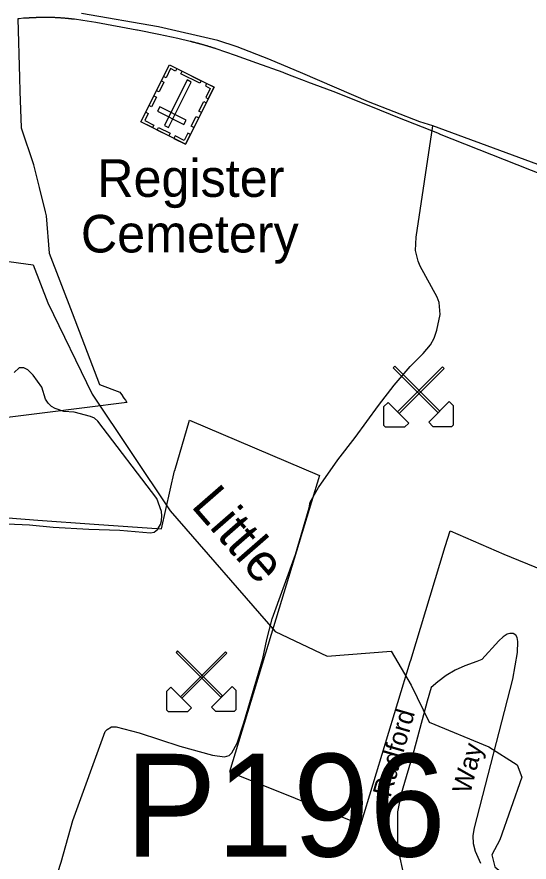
# Model space of a CAD drawing. Extents: x 2104537 to 2336408, y 34176 to 229611.
# Drawn here: x 2180556 to 2182600, y 64904 to 68278 of the extents above; entities that cross this region are included whole.
import ezdxf

# ---------------------------------------------------------------- set-up
doc = ezdxf.new("R2010")
doc.units = 0
for name, color, linetype in [('Exist Boundary Political City Limit New', 7, 'Continuous'), ('Exist Cultural Cemetery CELL', 7, 'Continuous'), ('Exist Cultural Cemetery Label', 7, 'Continuous'), ('Exist Geographical Pit Clay CELL', 7, 'Continuous'), ('Exist Hydrographic Creek Single Shore', 7, 'Continuous'), ('Exist Road Non-System Type 51', 7, 'Continuous'), ('Exist Road Non-System Type 51 Label', 7, 'Continuous'), ('Exist Road Secondary Structure Pipe Number Label', 7, 'Continuous'), ('Exist Road Secondary Type 51 Attributed', 7, 'Continuous'), ('Map Preparation Boundary City Limit Buffer Line', 7, 'Continuous'), ('Old_Level_32', 7, 'Continuous')]:
    doc.layers.add(name, color=color, linetype=linetype)

msp = doc.modelspace()

# ---------------------------------------------------------------- linework, layer by layer
at = {"layer": 'Exist Boundary Political City Limit New'}
for points in [[(2180745.8, 68272.1), (2180744, 68272.3), (2180741.8, 68272.5), (2180740, 68272.6), (2180738, 68272.8), (2180736, 68272.9), (2180734, 68273.1), (2180732, 68273.2), (2180730, 68273.4), (2180728, 68273.5), (2180726, 68273.6), (2180724, 68273.7), (2180722, 68273.9), (2180720, 68274), (2180718, 68274.1), (2180716, 68274.2), (2180714, 68274.3), (2180712, 68274.4), (2180710, 68274.5), (2180708, 68274.6), (2180706, 68274.7), (2180704, 68274.7), (2180702, 68274.8), (2180700, 68274.9), (2180698, 68275), (2180696, 68275), (2180694, 68275.1), (2180692, 68275.1), (2180690, 68275.2), (2180688, 68275.2), (2180686, 68275.2), (2180684, 68275.3), (2180682, 68275.3), (2180680, 68275.3), (2180678, 68275.4), (2180676, 68275.4), (2180673, 68275.4), (2180671, 68275.4), (2180669, 68275.4), (2180667, 68275.3), (2180665, 68275.3), (2180663, 68275.3), (2180661, 68275.3), (2180659, 68275.2), (2180657, 68275.2), (2180655, 68275.2), (2180653, 68275.1), (2180651, 68275.1), (2180649, 68275), (2180647, 68275), (2180645, 68275), (2180643, 68274.9), (2180641, 68274.8), (2180639, 68274.8), (2180637, 68274.7), (2180635, 68274.6), (2180633, 68274.6), (2180631, 68274.5), (2180629, 68274.4), (2180627, 68274.4), (2180625, 68274.3), (2180623, 68274.2), (2180621, 68274.1), (2180619, 68274), (2180617, 68273.9), (2180615, 68273.8), (2180613, 68273.7), (2180611, 68273.6), (2180609, 68273.5), (2180607, 68273.4), (2180606.2, 68273.4), (2180605, 68273.3), (2180603, 68273.2), (2180601.2, 68273.1), (2180599, 68273), (2180597, 68272.8), (2180595.2, 68272.7), (2180593.2, 68272.6), (2180591.2, 68272.5), (2180589.2, 68272.3), (2180587.2, 68272.2), (2180585.2, 68272.1), (2180582.2, 68271.9), (2180564.5, 68270.3), (2180559.2, 68269.8), (2180566.5, 68036), (2180568.2, 67979.9), (2180572.8, 67836.2), (2180573.2, 67835.2), (2180622.2, 67688.4), (2180622.5, 67687.7), (2180644.5, 67596.3), (2180668.5, 67500), (2180672.5, 67483.5), (2180672.5, 67482.9), (2180684.8, 67334.2), (2180776, 67096), (2180885.2, 66810.6), (2180966.8, 66779.9), (2180977.2, 66764.8)], [(2182711.5, 67624.2), (2182243, 67810), (2182242.2, 67810.3), (2182076.5, 67876), (2182047.8, 67887.6), (2182004.5, 67905), (2181922.5, 67938), (2181818, 67979.4), (2181717.8, 68017.1), (2181703.5, 68022.6), (2181654.8, 68041.6), (2181623.8, 68053.4), (2181619.2, 68055.1), (2181514, 68093.2), (2181428.8, 68123.9), (2181351, 68150.4), (2181349.2, 68151), (2181347.2, 68151.6), (2181345.2, 68152.2), (2181343.5, 68152.9), (2181341.5, 68153.4), (2181339.8, 68154), (2181337.8, 68154.6), (2181335.8, 68155.2), (2181334, 68155.8), (2181332, 68156.4), (2181330, 68157), (2181328.2, 68157.6), (2181326.2, 68158.2), (2181324.2, 68158.7), (2181322.5, 68159.3), (2181320.5, 68159.9), (2181318.5, 68160.5), (2181316.8, 68161), (2181314.8, 68161.6), (2181312.8, 68162.2), (2181311, 68162.7), (2181309, 68163.3), (2181307, 68163.8), (2181305.2, 68164.4), (2181303.2, 68164.9), (2181301.2, 68165.5), (2181299.5, 68166), (2181297.5, 68166.6), (2181295.5, 68167.1), (2181293.5, 68167.7), (2181291.8, 68168.2), (2181289.8, 68168.7), (2181287.8, 68169.2), (2181286, 68169.8), (2181284, 68170.3), (2181282, 68170.8), (2181280, 68171.4), (2181278.2, 68171.9), (2181276.2, 68172.4), (2181274.2, 68172.9), (2181272.5, 68173.4), (2181270.5, 68173.9), (2181268.5, 68174.4), (2181266.5, 68174.9), (2181264.8, 68175.4), (2181262.8, 68175.9), (2181260.8, 68176.4), (2181258.8, 68176.9), (2181257, 68177.4), (2181255, 68177.9), (2181253, 68178.4), (2181251, 68178.9), (2181247.2, 68179.8), (2181198.5, 68191.1), (2181122, 68207.9), (2181037.2, 68224), (2181034, 68224.6), (2180870.5, 68255.8), (2180819.5, 68263.4), (2180785.8, 68267.9), (2180783.8, 68268.1), (2180781.8, 68268.4), (2180779.8, 68268.6), (2180777.8, 68268.9), (2180775.8, 68269.1), (2180773.8, 68269.3), (2180771.8, 68269.5), (2180769.8, 68269.8), (2180767.8, 68270), (2180765.8, 68270.2), (2180763.8, 68270.4), (2180761.8, 68270.6), (2180759.8, 68270.8), (2180757.8, 68271), (2180755.8, 68271.2), (2180753.8, 68271.4), (2180751.8, 68271.6), (2180749.8, 68271.8), (2180747.8, 68272), (2180745.8, 68272.1)], [(2180977.2, 66764.8), (2180978, 66763.6), (2180983, 66756.2), (2180989, 66747.6), (2180995, 66738.8), (2180656.2, 66696.1), (2180281.5, 66648.9)], [(2180215.2, 66301.5), (2180639, 66269.3), (2180865, 66253.2), (2181133.5, 66234.1), (2181185.2, 66465.3), (2181185.8, 66467.5), (2181245.2, 66667.8), (2181763.8, 66447.4), (2181571, 65812), (2181404.8, 65263.7), (2181929.2, 65054), (2182126, 65702.8), (2182128, 65709.4), (2182265.8, 66163.1), (2182284.8, 66226.2), (2182500, 66133.2), (2182652.5, 66070.6)]]:
    msp.add_lwpolyline(points, dxfattribs=at)
at = {"layer": 'Exist Cultural Cemetery CELL'}
for points in [[(2181229, 67769.6), (2181050.9, 67858.7), (2181164.9, 68086.4), (2181342.9, 67997.3)], [(2181194.5, 68071.6), (2181189.4, 68061.3), (2181169.7, 68071.2), (2181151.6, 68035), (2181141.7, 68040), (2181164.9, 68086.4)], [(2181286.4, 68012.8), (2181210.5, 68050.7), (2181215.6, 68060.9), (2181291.5, 68023)], [(2181142.7, 68016.7), (2181123.3, 67978), (2181113.1, 67983.1), (2181132.5, 68021.8)], [(2181144.6, 67844.6), (2181161.3, 67836.2), (2181252, 68017.6), (2181235.3, 68025.9)], [(2181313.3, 68012.1), (2181308.2, 68001.8), (2181327.9, 67992), (2181309.8, 67955.8), (2181319.7, 67950.8), (2181342.9, 67997.2)], [(2181113.2, 67957.8), (2181093.8, 67919), (2181083.6, 67924.1), (2181103, 67962.9)], [(2181222.9, 67848.7), (2181231.3, 67865.4), (2181126, 67918.1), (2181117.6, 67901.4)], [(2181311.7, 67934.8), (2181292.3, 67896), (2181282.1, 67901.1), (2181301.5, 67939.8)], [(2181070.3, 67897.5), (2181080.4, 67892.4), (2181066, 67863.7), (2181102.3, 67845.5), (2181097.3, 67835.6), (2181050.9, 67858.8)], [(2181281.6, 67874.6), (2181262.2, 67835.9), (2181252, 67841), (2181271.4, 67879.7)], [(2181162.7, 67802.8), (2181116.4, 67826), (2181121.5, 67836.2), (2181167.8, 67813)], [(2181248.4, 67808.3), (2181238.2, 67813.4), (2181223.8, 67784.6), (2181187.5, 67802.8), (2181182.5, 67792.8), (2181229, 67769.6)]]:
    msp.add_lwpolyline(points, close=True, dxfattribs=at)
at = {"layer": 'Exist Geographical Pit Clay CELL'}
for points in [[(2182237.8, 66697.7), (2182243.6, 66703.5), (2182064, 66883.1), (2182058.2, 66877.3)], [(2182081.5, 66694.7), (2182075.7, 66700.5), (2182255.3, 66880.1), (2182261.1, 66874.3)], [(2182021, 66646.6), (2182021, 66722.3), (2182037.5, 66738.8), (2182119.8, 66656.5), (2182103.3, 66640), (2182027.6, 66640)], [(2182298.3, 66649.6), (2182298.3, 66725.3), (2182281.9, 66741.8), (2182199.6, 66659.5), (2182216, 66643), (2182291.7, 66643)], [(2181370.7, 65561.1), (2181376.6, 65566.9), (2181197, 65746.5), (2181191.2, 65740.7)], [(2181214.5, 65558.1), (2181208.7, 65563.9), (2181388.2, 65743.5), (2181394.1, 65737.7)], [(2181154, 65510), (2181154, 65585.7), (2181170.4, 65602.2), (2181252.7, 65519.9), (2181236.3, 65503.4), (2181160.5, 65503.4)], [(2181431.3, 65513), (2181431.3, 65588.7), (2181414.8, 65605.1), (2181332.5, 65522.8), (2181349, 65506.4), (2181424.7, 65506.4)]]:
    msp.add_lwpolyline(points, close=True, dxfattribs=at)
at = {"layer": 'Exist Hydrographic Creek Single Shore'}
msp.add_lwpolyline([(2179224.4, 66596.1), (2179424.4, 66713.7), (2179730.5, 67108), (2179879.4, 67200.3), (2180062.5, 67275.5), (2180395.5, 67318.3), (2180620.4, 67287.7), (2180679.5, 67135.6), (2180856.4, 66771.3), (2181167.5, 66306), (2181586.4, 65824.7), (2181795, 65725.9), (2182050.3, 65745.1), (2182129.8, 65610.5), (2182201.2, 65462.2), (2182440, 65363.4), (2182552.5, 65292), (2182571.7, 65242.5), (2182483.9, 64992.6), (2182451, 64932.2), (2182463.2, 64885.4), (2182494.9, 64858.1), (2182505.9, 64794.9), (2182559.6, 64740.4)], dxfattribs=at)
at = {"layer": 'Exist Road Non-System Type 51'}
for points in [[(2180690, 64771.2), (2180732.9, 64903.9), (2180779.4, 65070), (2180908.3, 65425.4), (2180916.4, 65433.5), (2180933.3, 65443.3), (2180952, 65443.9), (2181044.1, 65420.2), (2181206.7, 65365.9), (2181336.6, 65330.9), (2181385.1, 65324.4), (2181403.2, 65329.6), (2181413.3, 65339.6), (2181435, 65377.9), (2181462.2, 65460), (2181537.7, 65716.8), (2181553.2, 65792.9), (2181574.5, 65875.2), (2181668.4, 66131.9), (2181722.5, 66318.5), (2181726.2, 66340.8), (2181759.8, 66398.9), (2181836.8, 66509.6), (2181906.1, 66598.1), (2181998.8, 66726.9), (2182062.3, 66807.7), (2182125.5, 66882.3), (2182177, 66934.5), (2182206.8, 66969), (2182221.5, 66995.3), (2182232.3, 67027.2), (2182245.3, 67089.6), (2182241.3, 67137.3), (2182233.5, 67159.4), (2182166, 67282.8), (2182157.8, 67302.6), (2182147.5, 67344.5), (2182149.8, 67398.3), (2182216.5, 67842.2)], [(2180517.5, 66253.5), (2180605.7, 66249.9), (2180700.3, 66241.1), (2180843.2, 66232.8), (2180967.1, 66228.1), (2181089.6, 66217.9), (2181103.5, 66221.2), (2181116.5, 66231.8), (2181129, 66251.6), (2181132.9, 66265.6), (2181134.9, 66285.6), (2181132.6, 66303.7), (2181114.3, 66355.2), (2180879.4, 66663.6), (2180865.2, 66675.3), (2180849.6, 66682.5), (2180784.3, 66699.2), (2180743, 66702.3), (2180708.8, 66714.1), (2180694.2, 66721.9), (2180680.7, 66735.6), (2180670.5, 66751.6), (2180655, 66799.8), (2180621.5, 66847.3), (2180599.9, 66868.1), (2180583.6, 66877.3), (2180565.3, 66876.6), (2180545.6, 66858.7)], [(2182407.4, 64898.5), (2182386.7, 64946.1), (2182378.1, 64976.8), (2182376.7, 65009.9), (2182381.9, 65040), (2182534.8, 65633.6), (2182553.5, 65739.8), (2182555.4, 65783.8), (2182553.4, 65799.9), (2182547, 65809.5), (2182537.3, 65816.3), (2182522.9, 65816.5), (2182513, 65813.4), (2182497, 65803.3), (2182479.3, 65786.9), (2182411.9, 65712.4), (2182391.2, 65703.9), (2182343.5, 65687.2), (2182305.3, 65670.5), (2182269.5, 65649), (2182236.1, 65622.7), (2182209.9, 65601.3), (2182193.2, 65546.3), (2182140.7, 65348.2), (2182089.4, 65176.3), (2182075.1, 65104.7), (2182075.1, 64963.9), (2182112.5, 64793.3)]]:
    msp.add_lwpolyline(points, dxfattribs=at)
at = {"layer": 'Exist Road Secondary Type 51 Attributed'}
msp.add_lwpolyline([(2185228.9, 67698.8), (2184857.8, 67518.4), (2184683.7, 67443.7), (2184607, 67414.7), (2184546.9, 67402.2), (2184466.1, 67391.9), (2184304.4, 67381.5), (2183989.9, 67371.1), (2183730.8, 67364.9), (2183627.2, 67362.8), (2183554.6, 67364.9), (2183475.8, 67379.4), (2183388.8, 67398.1), (2183287.2, 67435.4), (2182928.6, 67580.6), (2182216.5, 67842.2), (2182164.3, 67859.3), (2181959.8, 67938.3), (2181697.2, 68051.6), (2181562.1, 68108.7), (2181434.6, 68158.2), (2181358.5, 68183), (2181120.6, 68238.2), (2180814.2, 68291.5)], dxfattribs=at)
at = {"layer": 'Map Preparation Boundary City Limit Buffer Line'}
for points in [[(2180745.8, 68272.1), (2180744, 68272.3), (2180741.8, 68272.5), (2180740, 68272.6), (2180738, 68272.8), (2180736, 68272.9), (2180734, 68273.1), (2180732, 68273.2), (2180730, 68273.4), (2180728, 68273.5), (2180726, 68273.6), (2180724, 68273.7), (2180722, 68273.9), (2180720, 68274), (2180718, 68274.1), (2180716, 68274.2), (2180714, 68274.3), (2180712, 68274.4), (2180710, 68274.5), (2180708, 68274.6), (2180706, 68274.7), (2180704, 68274.7), (2180702, 68274.8), (2180700, 68274.9), (2180698, 68275), (2180696, 68275), (2180694, 68275.1), (2180692, 68275.1), (2180690, 68275.2), (2180688, 68275.2), (2180686, 68275.2), (2180684, 68275.3), (2180682, 68275.3), (2180680, 68275.3), (2180678, 68275.4), (2180676, 68275.4), (2180673, 68275.4), (2180671, 68275.4), (2180669, 68275.4), (2180667, 68275.3), (2180665, 68275.3), (2180663, 68275.3), (2180661, 68275.3), (2180659, 68275.2), (2180657, 68275.2), (2180655, 68275.2), (2180653, 68275.1), (2180651, 68275.1), (2180649, 68275), (2180647, 68275), (2180645, 68275), (2180643, 68274.9), (2180641, 68274.8), (2180639, 68274.8), (2180637, 68274.7), (2180635, 68274.6), (2180633, 68274.6), (2180631, 68274.5), (2180629, 68274.4), (2180627, 68274.4), (2180625, 68274.3), (2180623, 68274.2), (2180621, 68274.1), (2180619, 68274), (2180617, 68273.9), (2180615, 68273.8), (2180613, 68273.7), (2180611, 68273.6), (2180609, 68273.5), (2180607, 68273.4), (2180606.2, 68273.4), (2180605, 68273.3), (2180603, 68273.2), (2180601.2, 68273.1), (2180599, 68273), (2180597, 68272.8), (2180595.2, 68272.7), (2180593.2, 68272.6), (2180591.2, 68272.5), (2180589.2, 68272.3), (2180587.2, 68272.2), (2180585.2, 68272.1), (2180582.2, 68271.9), (2180564.5, 68270.3), (2180559.2, 68269.8), (2180566.5, 68036), (2180568.2, 67979.9), (2180572.8, 67836.2), (2180573.2, 67835.2), (2180622.2, 67688.4), (2180622.5, 67687.7), (2180644.5, 67596.3), (2180668.5, 67500), (2180672.5, 67483.5), (2180672.5, 67482.9), (2180684.8, 67334.2), (2180776, 67096), (2180885.2, 66810.6), (2180966.8, 66779.9), (2180977.2, 66764.8)], [(2182711.5, 67624.2), (2182243, 67810), (2182242.2, 67810.3), (2182076.5, 67876), (2182047.8, 67887.6), (2182004.5, 67905), (2181922.5, 67938), (2181818, 67979.4), (2181717.8, 68017.1), (2181703.5, 68022.6), (2181654.8, 68041.6), (2181623.8, 68053.4), (2181619.2, 68055.1), (2181514, 68093.2), (2181428.8, 68123.9), (2181351, 68150.4), (2181349.2, 68151), (2181347.2, 68151.6), (2181345.2, 68152.2), (2181343.5, 68152.9), (2181341.5, 68153.4), (2181339.8, 68154), (2181337.8, 68154.6), (2181335.8, 68155.2), (2181334, 68155.8), (2181332, 68156.4), (2181330, 68157), (2181328.2, 68157.6), (2181326.2, 68158.2), (2181324.2, 68158.7), (2181322.5, 68159.3), (2181320.5, 68159.9), (2181318.5, 68160.5), (2181316.8, 68161), (2181314.8, 68161.6), (2181312.8, 68162.2), (2181311, 68162.7), (2181309, 68163.3), (2181307, 68163.8), (2181305.2, 68164.4), (2181303.2, 68164.9), (2181301.2, 68165.5), (2181299.5, 68166), (2181297.5, 68166.6), (2181295.5, 68167.1), (2181293.5, 68167.7), (2181291.8, 68168.2), (2181289.8, 68168.7), (2181287.8, 68169.2), (2181286, 68169.8), (2181284, 68170.3), (2181282, 68170.8), (2181280, 68171.4), (2181278.2, 68171.9), (2181276.2, 68172.4), (2181274.2, 68172.9), (2181272.5, 68173.4), (2181270.5, 68173.9), (2181268.5, 68174.4), (2181266.5, 68174.9), (2181264.8, 68175.4), (2181262.8, 68175.9), (2181260.8, 68176.4), (2181258.8, 68176.9), (2181257, 68177.4), (2181255, 68177.9), (2181253, 68178.4), (2181251, 68178.9), (2181247.2, 68179.8), (2181198.5, 68191.1), (2181122, 68207.9), (2181037.2, 68224), (2181034, 68224.6), (2180870.5, 68255.8), (2180819.5, 68263.4), (2180785.8, 68267.9), (2180783.8, 68268.1), (2180781.8, 68268.4), (2180779.8, 68268.6), (2180777.8, 68268.9), (2180775.8, 68269.1), (2180773.8, 68269.3), (2180771.8, 68269.5), (2180769.8, 68269.8), (2180767.8, 68270), (2180765.8, 68270.2), (2180763.8, 68270.4), (2180761.8, 68270.6), (2180759.8, 68270.8), (2180757.8, 68271), (2180755.8, 68271.2), (2180753.8, 68271.4), (2180751.8, 68271.6), (2180749.8, 68271.8), (2180747.8, 68272), (2180745.8, 68272.1)], [(2180977.2, 66764.8), (2180978, 66763.6), (2180983, 66756.2), (2180989, 66747.6), (2180995, 66738.8), (2180656.2, 66696.1), (2180281.5, 66648.9)], [(2180215.2, 66301.5), (2180639, 66269.3), (2180865, 66253.2), (2181133.5, 66234.1), (2181185.2, 66465.3), (2181185.8, 66467.5), (2181245.2, 66667.8), (2181763.8, 66447.4), (2181571, 65812), (2181404.8, 65263.7), (2181929.2, 65054), (2182126, 65702.8), (2182128, 65709.4), (2182265.8, 66163.1), (2182284.8, 66226.2), (2182500, 66133.2), (2182652.5, 66070.6)]]:
    msp.add_lwpolyline(points, dxfattribs=at)

# ---------------------------------------------------------------- texts
at = {"layer": 'Exist Cultural Cemetery Label'}
for s, p in [('Register', (2180876.7, 67559.2)), ('Cemetery', (2180811.4, 67337.2))]:
    msp.add_text(s, height=150, dxfattribs=at).set_placement(p)
at = {"layer": 'Exist Road Non-System Type 51 Label'}
for s, rotation, p in [('Radford', 73.9113, (2182046.7, 65158.2)), ('Way', 75.5578, (2182365.3, 65172.7))]:
    msp.add_text(s, height=75, rotation=rotation, dxfattribs=at).set_placement(p)
at = {"layer": 'Exist Road Secondary Structure Pipe Number Label'}
msp.add_text('P196', height=410.1, dxfattribs=at).set_placement((2180987.1, 64925.9))
at = {"layer": 'Old_Level_32'}
msp.add_text('Little', height=150, rotation=311.0813, dxfattribs=at).set_placement((2181247.6, 66323.9))

doc.saveas('drawing.dxf')
